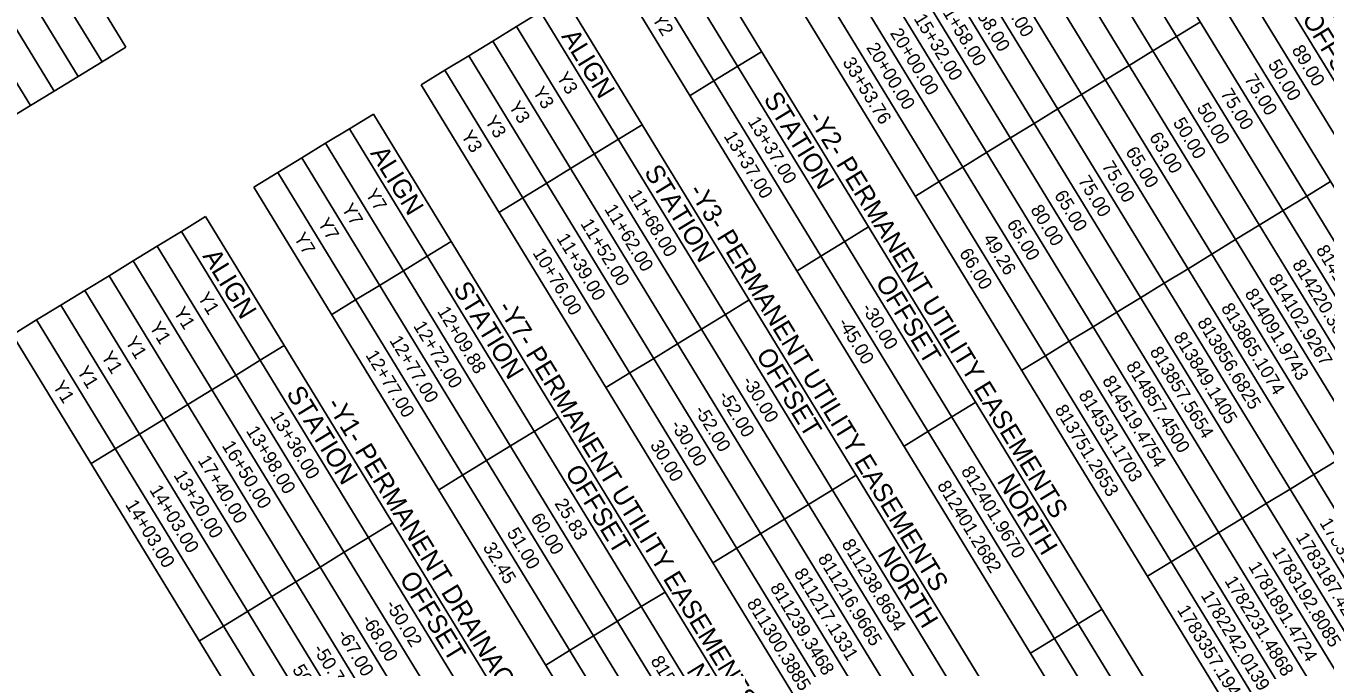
# Model space of a CAD drawing. Extents: x 1753086 to 1770987, y 792577 to 812636.
# Drawn here: x 1760334 to 1764623, y 800134 to 802249 of the extents above; entities that cross this region are included whole.
import ezdxf

# ---------------------------------------------------------------- set-up
doc = ezdxf.new("R2010")
doc.units = 0
for name, color, linetype in [('CTL Sheet Notes CELL', 7, 'Continuous'), ('CTL Sheet Table Cell', 7, 'Continuous'), ('CTL Sheet Text', 7, 'Continuous'), ('Old_Level_2', 7, 'Continuous')]:
    doc.layers.add(name, color=color, linetype=linetype)

msp = doc.modelspace()

# ---------------------------------------------------------------- linework, layer by layer
at = {"layer": 'CTL Sheet Table Cell'}
for p, q in [((1758865.6, 805122.1), (1760664.2, 802178.5)), ((1758786.8, 805073.9), (1760585.4, 802130.3)), ((1758707.9, 805025.8), (1760506.5, 802082.1)), ((1758629.1, 804977.6), (1760427.7, 802034)), ((1758550.3, 804929.4), (1760348.8, 801985.8)), ((1763839.7, 803399.1), (1765628, 800472.2)), ((1763761.3, 803351.2), (1765549.6, 800424.3)), ((1763682.9, 803303.3), (1765471.2, 800376.4)), ((1763604.5, 803255.4), (1765392.8, 800328.5)), ((1763526.1, 803207.5), (1765314.4, 800280.6)), ((1763447.7, 803159.6), (1765236, 800232.7)), ((1763369.3, 803111.7), (1765157.6, 800184.8)), ((1763290.9, 803063.8), (1765079.2, 800136.9)), ((1763212.5, 803015.9), (1765000.8, 800089)), ((1763134.1, 802968), (1764922.4, 800041.1)), ((1763055.7, 802920.1), (1764844, 799993.2)), ((1762977.3, 802872.2), (1764765.6, 799945.3)), ((1762898.9, 802824.3), (1764687.2, 799897.4)), ((1762820.5, 802776.4), (1764608.8, 799849.5)), ((1762742.1, 802728.5), (1764530.4, 799801.6)), ((1762663.7, 802680.6), (1764452, 799753.7)), ((1762506, 802584.3), (1764304.5, 799640.6)), ((1762427.1, 802536.1), (1764225.7, 799592.5)), ((1762348.3, 802487.9), (1764146.8, 799544.3)), ((1762269.4, 802439.7), (1764068, 799496.1)), ((1762111.7, 802343.4), (1763910.3, 799399.7)), ((1762032.9, 802295.2), (1761954, 802247)), ((1762032.9, 802295.2), (1763831.5, 799351.6)), ((1761954, 802247), (1761875.2, 802198.8)), ((1761954, 802247), (1763752.6, 799303.4)), ((1764211.2, 802262.4), (1764132.8, 802214.5)), ((1761875.2, 802198.8), (1761796.4, 802150.7)), ((1761875.2, 802198.8), (1763673.8, 799255.2)), ((1764132.8, 802214.5), (1764054.4, 802166.6)), ((1760664.2, 802178.5), (1760585.4, 802130.3)), ((1761796.4, 802150.7), (1761717.5, 802102.5)), ((1761796.4, 802150.7), (1763594.9, 799207)), ((1762762.9, 802163.7), (1762684.1, 802115.6)), ((1764054.4, 802166.6), (1763976, 802118.7)), ((1760585.4, 802130.3), (1760506.5, 802082.1)), ((1761717.5, 802102.5), (1761638.7, 802054.3)), ((1761717.5, 802102.5), (1763516.1, 799158.9)), ((1762684.1, 802115.6), (1762605.2, 802067.4)), ((1763976, 802118.7), (1763897.6, 802070.8)), ((1760506.5, 802082.1), (1760427.7, 802034)), ((1762605.2, 802067.4), (1762526.4, 802019.2)), ((1763897.6, 802070.8), (1763819.2, 802022.9)), ((1760427.7, 802034), (1760348.8, 801985.8)), ((1761638.7, 802054.3), (1763437.2, 799110.7)), ((1763819.2, 802022.9), (1763740.8, 801975)), ((1760348.8, 801985.8), (1760270, 801937.6)), ((1763740.8, 801975), (1763662.4, 801927.1)), ((1761481, 801958), (1761402.1, 801909.8)), ((1761481, 801958), (1763279.5, 799014.3)), ((1761402.1, 801909.8), (1761323.3, 801861.6)), ((1761402.1, 801909.8), (1763200.7, 798966.2)), ((1762368.7, 801922.9), (1762289.8, 801874.7)), ((1763662.4, 801927.1), (1763584, 801879.2)), ((1761323.3, 801861.6), (1761244.4, 801813.4)), ((1761323.3, 801861.6), (1763121.8, 798918)), ((1762289.8, 801874.7), (1762211, 801826.5)), ((1763584, 801879.2), (1763505.6, 801831.3)), ((1761244.4, 801813.4), (1761165.6, 801765.3)), ((1761244.4, 801813.4), (1763043, 798869.8)), ((1762211, 801826.5), (1762132.1, 801778.3)), ((1763505.6, 801831.3), (1763427.2, 801783.4)), ((1761165.6, 801765.3), (1761086.7, 801717.1)), ((1761165.6, 801765.3), (1762964.1, 798821.6)), ((1762132.1, 801778.3), (1762053.3, 801730.2)), ((1763427.2, 801783.4), (1763348.8, 801735.4)), ((1761086.7, 801717.1), (1762885.3, 798773.5)), ((1762053.3, 801730.2), (1761974.4, 801682)), ((1763348.8, 801735.4), (1763270.4, 801687.5)), ((1764640.9, 801735.3), (1764562.5, 801687.4)), ((1761974.4, 801682), (1761895.6, 801633.8)), ((1764562.5, 801687.4), (1764484.1, 801639.5)), ((1764484.1, 801639.5), (1764405.7, 801591.6)), ((1760927.2, 801619.6), (1760847.5, 801570.9)), ((1760927.2, 801619.6), (1762746.2, 798642.6)), ((1764405.7, 801591.6), (1764327.3, 801543.7)), ((1760847.5, 801570.9), (1760767.8, 801522.2)), ((1760847.5, 801570.9), (1762666.5, 798593.8)), ((1763116.2, 801585.5), (1763037.4, 801537.3)), ((1760767.8, 801522.2), (1760688, 801473.5)), ((1760767.8, 801522.2), (1762586.8, 798545.1)), ((1761737.9, 801537.5), (1761659.1, 801489.3)), ((1763037.4, 801537.3), (1762958.5, 801489.2)), ((1764327.3, 801543.7), (1764248.9, 801495.8)), ((1760688, 801473.5), (1760608.3, 801424.8)), ((1760688, 801473.5), (1762507, 798496.4)), ((1761659.1, 801489.3), (1761580.2, 801441.1)), ((1762958.5, 801489.2), (1762879.7, 801441)), ((1764248.9, 801495.8), (1764170.5, 801447.9)), ((1760608.3, 801424.8), (1760528.5, 801376)), ((1760608.3, 801424.8), (1762427.3, 798447.7)), ((1761580.2, 801441.1), (1761501.4, 801392.9)), ((1764170.5, 801447.9), (1764092.1, 801400)), ((1760528.5, 801376), (1760448.8, 801327.3)), ((1760528.5, 801376), (1762347.5, 798399)), ((1761501.4, 801392.9), (1761422.5, 801344.7)), ((1764092.1, 801400), (1764013.7, 801352.1)), ((1761422.5, 801344.7), (1761343.7, 801296.6)), ((1762722, 801344.6), (1762643.1, 801296.5)), ((1764013.7, 801352.1), (1763935.3, 801304.2)), ((1760448.8, 801327.3), (1760369, 801278.6)), ((1760448.8, 801327.3), (1762267.8, 798350.2)), ((1762643.1, 801296.5), (1762564.3, 801248.3)), ((1763935.3, 801304.2), (1763856.9, 801256.3)), ((1760369, 801278.6), (1760289.3, 801229.9)), ((1760369, 801278.6), (1762188, 798301.5)), ((1762564.3, 801248.3), (1762485.4, 801200.1)), ((1763856.9, 801256.3), (1763778.5, 801208.4)), ((1760289.3, 801229.9), (1762108.3, 798252.8)), ((1763778.5, 801208.4), (1763700.1, 801160.5)), ((1761187.1, 801194.3), (1761107.4, 801145.6)), ((1762485.4, 801200.1), (1762406.6, 801151.9)), ((1763700.1, 801160.5), (1763621.7, 801112.6)), ((1761107.4, 801145.6), (1761027.6, 801096.9)), ((1762406.6, 801151.9), (1762327.7, 801103.8)), ((1761027.6, 801096.9), (1760947.9, 801048.2)), ((1762327.7, 801103.8), (1762248.9, 801055.6)), ((1760947.9, 801048.2), (1760868.1, 800999.5)), ((1760868.1, 800999.5), (1760788.4, 800950.7)), ((1763469.5, 801007.3), (1763390.6, 800959.1)), ((1760788.4, 800950.7), (1760708.6, 800902)), ((1762091.2, 800959.2), (1762012.3, 800911.1)), ((1763390.6, 800959.1), (1763311.8, 800911)), ((1760708.6, 800902), (1760628.9, 800853.3)), ((1762012.3, 800911.1), (1761933.5, 800862.9)), ((1763311.8, 800911), (1763232.9, 800862.8)), ((1761933.5, 800862.9), (1761854.6, 800814.7)), ((1760628.9, 800853.3), (1760549.2, 800804.6)), ((1764664.1, 800816.4), (1764585.7, 800768.5)), ((1761854.6, 800814.7), (1761775.8, 800766.5)), ((1761775.8, 800766.5), (1761697, 800718.4)), ((1763075.3, 800766.4), (1762996.4, 800718.3)), ((1764585.7, 800768.5), (1764507.3, 800720.6)), ((1762996.4, 800718.3), (1762917.6, 800670.1)), ((1764507.3, 800720.6), (1764428.9, 800672.7)), ((1762917.6, 800670.1), (1762838.7, 800621.9)), ((1764428.9, 800672.7), (1764350.5, 800624.8)), ((1761544.4, 800609.6), (1761464.7, 800560.8)), ((1762838.7, 800621.9), (1762759.9, 800573.7)), ((1764350.5, 800624.8), (1764272.1, 800576.9)), ((1761464.7, 800560.8), (1761384.9, 800512.1)), ((1762759.9, 800573.7), (1762681, 800525.6)), ((1764272.1, 800576.9), (1764193.7, 800529)), ((1762681, 800525.6), (1762602.2, 800477.4)), ((1764193.7, 800529), (1764115.3, 800481.1)), ((1761384.9, 800512.1), (1761305.2, 800463.4)), ((1764115.3, 800481.1), (1764036.9, 800433.2)), ((1761305.2, 800463.4), (1761225.4, 800414.7)), ((1761225.4, 800414.7), (1761145.7, 800365.9)), ((1761145.7, 800365.9), (1761065.9, 800317.2)), ((1762444.5, 800381), (1762365.6, 800332.9)), ((1761065.9, 800317.2), (1760986.2, 800268.5)), ((1762365.6, 800332.9), (1762286.8, 800284.7)), ((1763887, 800324), (1763808.2, 800275.8)), ((1760986.2, 800268.5), (1760906.5, 800219.8)), ((1762286.8, 800284.7), (1762207.9, 800236.5)), ((1763808.2, 800275.8), (1763729.3, 800227.6)), ((1762207.9, 800236.5), (1762129.1, 800188.3)), ((1763729.3, 800227.6), (1763650.5, 800179.4)), ((1762129.1, 800188.3), (1762050.2, 800140.1))]:
    msp.add_line(p, q, dxfattribs=at)

# ---------------------------------------------------------------- texts
at = {"layer": 'CTL Sheet Notes CELL'}
for s, height, p in [('-Y1- PERMANENT UTILITY EASEMENTS', 61.25, (1764323.6, 802812.6)), ('OFFSET', 61.25, (1764545.4, 802273.5)), ('ALIGN', 61.6, (1762100.2, 802214.7)), ('STATION', 61.6, (1762767.6, 802008.3)), ('-Y2- PERMANENT UTILITY EASEMENTS', 61.6, (1762913.9, 801946.2)), ('ALIGN', 61.6, (1761469.4, 801829.2)), ('STATION', 61.6, (1762373.4, 801767.4)), ('-Y3- PERMANENT UTILITY EASEMENTS', 61.6, (1762519.6, 801705.3)), ('ALIGN', 62.3, (1760915.5, 801489.5)), ('OFFSET', 61.6, (1763136.9, 801404)), ('STATION', 61.6, (1761742.6, 801382)), ('-Y7- PERMANENT UTILITY EASEMENTS', 61.6, (1761888.9, 801319.9)), ('OFFSET', 61.6, (1762742.6, 801163.2)), ('STATION', 62.3, (1761191.9, 801037.2)), ('-Y1- PERMANENT DRAINAGE EASEMENTS', 62.3, (1761323.7, 801000.7)), ('OFFSET', 61.6, (1762111.8, 800777.7)), ('NORTH', 61.6, (1763538.2, 800747.2)), ('NORTH', 61.6, (1763144, 800506.3)), ('OFFSET', 62.3, (1761565.3, 800426)), ('NORTH', 61.6, (1762513.2, 800120.9))]:
    msp.add_text(s, height=height, rotation=301.4249, dxfattribs=at).set_placement(p)
at = {"layer": 'CTL Sheet Text'}
for s, height, p in [('31+44.00', 43.75, (1763499, 802417)), ('31+58.00', 43.75, (1763420.6, 802369)), ('31+58.00', 43.75, (1763342.2, 802321.1)), ('Y2', 44, (1762399.6, 802273.1)), ('15+32.00', 43.75, (1763263.8, 802273.2)), ('20+00.00', 43.75, (1763185.4, 802225.3)), ('20+00.00', 43.75, (1763107, 802177.4)), ('33+53.76', 43.75, (1763028.6, 802129.5)), ('89.00', 43.75, (1764511.4, 802169.7)), ('Y3', 44, (1762084.2, 802080.4)), ('50.00', 43.75, (1764433, 802121.8)), ('75.00', 43.75, (1764354.6, 802073.9)), ('Y3', 44, (1762005.4, 802032.2)), ('75.00', 43.75, (1764276.2, 802026)), ('Y3', 44, (1761926.5, 801984.1)), ('50.00', 43.75, (1764197.8, 801978.1)), ('Y3', 44, (1761847.7, 801935.9)), ('13+37.00', 44, (1762715.3, 801933.7)), ('50.00', 43.75, (1764119.4, 801930.2)), ('Y3', 44, (1761768.8, 801887.7)), ('13+37.00', 44, (1762636.4, 801885.5)), ('63.00', 43.75, (1764041, 801882.3)), ('65.00', 43.75, (1763962.6, 801834.4)), ('75.00', 43.75, (1763884.2, 801786.5)), ('Y7', 44, (1761453.4, 801695)), ('75.00', 43.75, (1763805.8, 801738.6)), ('11+68.00', 44, (1762321, 801692.8)), ('65.00', 43.75, (1763727.4, 801690.7)), ('Y7', 44, (1761374.6, 801646.8)), ('11+62.00', 44, (1762242.2, 801644.6)), ('80.00', 43.75, (1763649, 801642.8)), ('Y7', 44, (1761295.7, 801598.7)), ('11+52.00', 44, (1762163.3, 801596.5)), ('65.00', 43.75, (1763570.6, 801594.9)), ('Y7', 44, (1761216.9, 801550.5)), ('11+39.00', 44, (1762084.5, 801548.3)), ('49.26', 43.75, (1763492.2, 801547)), ('10+76.00', 44, (1762005.6, 801500.1)), ('66.00', 43.75, (1763413.8, 801499.1)), ('814199.3038', 43.75, (1764591.5, 801509.9)), ('814220.3661', 43.75, (1764513.1, 801462)), ('814102.9267', 43.75, (1764434.7, 801414.1)), ('Y1', 44.5, (1760899.4, 801353.7)), ('814091.9743', 43.75, (1764356.3, 801366.2)), ('813865.1074', 43.75, (1764277.9, 801318.3)), ('Y1', 44.5, (1760819.6, 801305)), ('12+09.88', 44, (1761690.3, 801307.4)), ('-30.00', 44, (1763091.3, 801318.2)), ('813856.6825', 43.75, (1764199.5, 801270.4)), ('Y1', 44.5, (1760739.9, 801256.3)), ('12+72.00', 44, (1761611.4, 801259.2)), ('-45.00', 44, (1763012.5, 801270)), ('Y1', 44.5, (1760660.2, 801207.5)), ('12+77.00', 44, (1761532.6, 801211.1)), ('813849.1405', 43.75, (1764121.1, 801222.5)), ('Y1', 44.5, (1760580.4, 801158.8)), ('12+77.00', 44, (1761453.7, 801162.9)), ('813857.5654', 43.75, (1764042.7, 801174.6)), ('Y1', 44.5, (1760500.7, 801110.1)), ('814857.4500', 43.75, (1763964.3, 801126.7)), ('Y1', 44.5, (1760420.9, 801061.4)), ('-30.00', 44, (1762697.1, 801077.3)), ('814519.4754', 43.75, (1763885.9, 801078.8)), ('-52.00', 44, (1762618.2, 801029.2)), ('814531.1703', 43.75, (1763807.5, 801030.9)), ('-52.00', 44, (1762539.4, 800981)), ('813751.2653', 43.75, (1763729.1, 800983)), ('13+36.00', 44.5, (1761138.9, 800961.7)), ('13+98.00', 44.5, (1761059.2, 800913)), ('-30.00', 44, (1762460.5, 800932.8)), ('16+50.00', 44.5, (1760979.4, 800864.2)), ('30.00', 44, (1762393.1, 800866)), ('17+40.00', 44.5, (1760899.7, 800815.5)), ('13+20.00', 44.5, (1760819.9, 800766.8)), ('812401.9670', 44, (1763419.8, 800780.6)), ('14+03.00', 44.5, (1760740.2, 800718.1)), ('812401.2682', 44, (1763341, 800732.4)), ('25.83', 44, (1762077.7, 800673.3)), ('14+03.00', 44.5, (1760660.5, 800669.3)), ('60.00', 44, (1761998.8, 800625.1)), ('1783175.6265', 43.75, (1764603.3, 800609.4)), ('51.00', 44, (1761920, 800577)), ('1783187.4214', 43.75, (1764524.9, 800561.5)), ('32.45', 44, (1761841.1, 800528.8)), ('811238.8634', 44, (1763025.6, 800539.7)), ('1783192.8085', 43.75, (1764446.6, 800513.6)), ('811216.9665', 44, (1762946.7, 800491.5)), ('1781891.4724', 43.75, (1764368.2, 800465.7)), ('811217.1331', 44, (1762867.9, 800443.3)), ('1782231.4868', 43.75, (1764289.8, 800417.8)), ('811239.3468', 44, (1762789, 800395.2)), ('-50.02', 44.5, (1761519.2, 800339.2)), ('811300.3885', 44, (1762712.2, 800343.7)), ('1782242.0139', 43.75, (1764211.4, 800369.9)), ('1783357.1943', 43.75, (1764133, 800322)), ('-68.00', 44.5, (1761439.5, 800290.5)), ('-67.00', 44.5, (1761359.7, 800241.8)), ('-50.70', 44.5, (1761280, 800193.1)), ('50.00', 44.5, (1761211.8, 800125.5)), ('815674.5829', 44, (1762394.8, 800154.3))]:
    msp.add_text(s, height=height, rotation=301.4249, dxfattribs=at).set_placement(p)
at = {"layer": 'Old_Level_2'}
msp.add_text('1. THE CONTROL DATA FOR THIS PROJECT CAN BE FOUND ELECTRONICALLY', height=60, rotation=301.4249, dxfattribs=at).set_placement((1759202.6, 800357.2))

doc.saveas('drawing.dxf')
